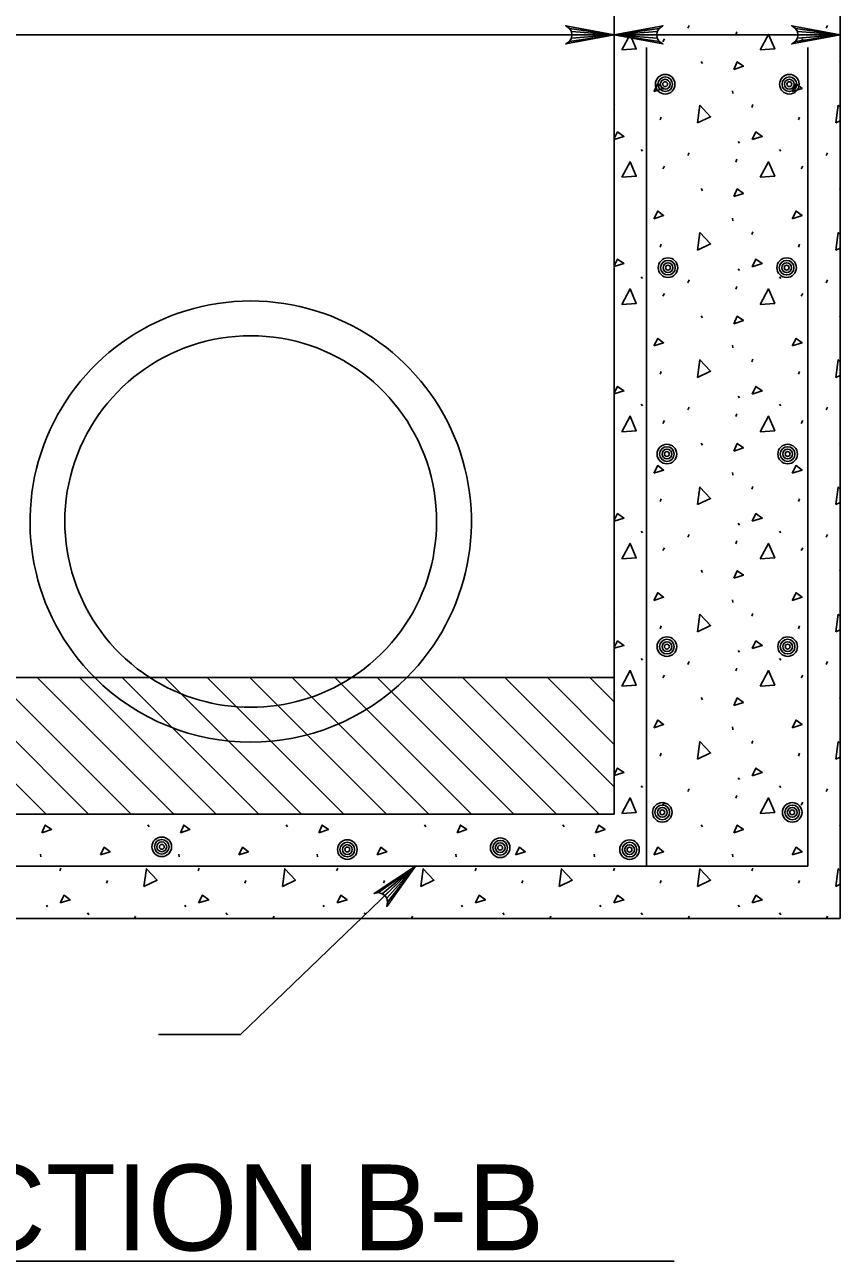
# Model space of a CAD drawing. Extents: x 6.91 to 13.84, y 0.35 to 9.99.
# Drawn here: x 8.532 to 9.481, y 2.3 to 3.739 of the extents above; entities that cross this region are included whole.
import ezdxf

# ---------------------------------------------------------------- set-up
doc = ezdxf.new("R2010")
doc.units = 0
for name, color, linetype in [('Default', 7, 'Continuous'), ('DETL-DIMS', 7, 'Continuous'), ('DETL-LINE', 7, 'Continuous'), ('DETL-TITL', 7, 'Continuous')]:
    doc.layers.add(name, color=color, linetype=linetype)

msp = doc.modelspace()

# ---------------------------------------------------------------- linework, layer by layer
at = {"layer": 'Default'}
for p, q in [((9.3039, 3.7353), (9.3055, 3.7386)), ((9.3599, 3.7277), (9.3611, 3.7309)), ((9.465, 3.7353), (9.4666, 3.7386)), ((9.2749, 3.7196), (9.2766, 3.7229)), ((9.436, 3.7196), (9.4376, 3.7229)), ((9.3196, 3.6967), (9.3212, 3.6943)), ((9.4807, 3.6967), (9.4813, 3.6957)), ((9.3559, 3.6625), (9.3563, 3.6593)), ((9.2184, 3.6458), (9.2186, 3.6464)), ((9.3784, 3.6431), (9.3796, 3.6464)), ((9.2717, 3.6287), (9.2729, 3.6319)), ((9.4328, 3.6287), (9.434, 3.6319)), ((9.4813, 3.6274), (9.4762, 3.625)), ((9.3627, 3.6033), (9.3639, 3.6013)), ((9.2496, 3.594), (9.2512, 3.592)), ((9.3039, 3.5872), (9.3055, 3.5904)), ((9.4106, 3.594), (9.4122, 3.592)), ((9.465, 3.5872), (9.4666, 3.5904)), ((9.2749, 3.5715), (9.2766, 3.5747)), ((9.3599, 3.5795), (9.3611, 3.5828)), ((9.436, 3.5715), (9.4376, 3.5747)), ((9.3196, 3.5485), (9.3212, 3.5461)), ((9.4807, 3.5485), (9.4813, 3.5476)), ((9.3559, 3.5143), (9.3563, 3.5111)), ((9.2184, 3.4977), (9.2186, 3.4982)), ((9.3784, 3.495), (9.3796, 3.4982)), ((9.2717, 3.4805), (9.2729, 3.4837)), ((9.4328, 3.4805), (9.434, 3.4837)), ((9.4813, 3.4793), (9.4762, 3.4769)), ((9.2496, 3.4459), (9.2512, 3.4439)), ((9.3039, 3.439), (9.3055, 3.4423)), ((9.3627, 3.4551), (9.3639, 3.4531)), ((9.4106, 3.4459), (9.4122, 3.4439)), ((9.465, 3.439), (9.4666, 3.4423)), ((9.3599, 3.4314), (9.3611, 3.4346)), ((9.2749, 3.4233), (9.2766, 3.4266)), ((9.436, 3.4233), (9.4376, 3.4266)), ((9.3196, 3.4004), (9.3212, 3.398)), ((9.4807, 3.4004), (9.4813, 3.3994)), ((9.3559, 3.3662), (9.3563, 3.363)), ((9.2184, 3.3495), (9.2186, 3.3501)), ((9.3784, 3.3469), (9.3796, 3.3501)), ((9.2717, 3.3324), (9.2729, 3.3356)), ((9.4328, 3.3324), (9.434, 3.3356)), ((9.4813, 3.3311), (9.4762, 3.3287)), ((9.2496, 3.2977), (9.2512, 3.2957)), ((9.3627, 3.307), (9.3639, 3.305)), ((9.4106, 3.2977), (9.4122, 3.2957)), ((9.3039, 3.2909), (9.3055, 3.2941)), ((9.3599, 3.2832), (9.3611, 3.2865)), ((9.465, 3.2909), (9.4666, 3.2941)), ((9.2749, 3.2752), (9.2766, 3.2784)), ((9.436, 3.2752), (9.4376, 3.2784)), ((9.3196, 3.2522), (9.3212, 3.2498)), ((9.4807, 3.2522), (9.4813, 3.2513)), ((9.3559, 3.218), (9.3563, 3.2148)), ((9.2184, 3.2014), (9.2186, 3.2019)), ((9.3784, 3.1987), (9.3796, 3.2019)), ((9.2717, 3.1842), (9.2729, 3.1874)), ((9.4328, 3.1842), (9.434, 3.1874)), ((9.4813, 3.183), (9.4762, 3.1806)), ((9.3627, 3.1589), (9.3639, 3.1568)), ((9.2496, 3.1496), (9.2512, 3.1476)), ((9.3039, 3.1427), (9.3055, 3.146)), ((9.4106, 3.1496), (9.4122, 3.1476)), ((9.465, 3.1427), (9.4666, 3.146)), ((9.2749, 3.127), (9.2766, 3.1303)), ((9.3599, 3.1351), (9.3611, 3.1383)), ((9.436, 3.127), (9.4376, 3.1303)), ((9.3196, 3.1041), (9.3212, 3.1017)), ((9.4807, 3.1041), (9.4813, 3.1031)), ((9.3559, 3.0699), (9.3563, 3.0667)), ((9.2184, 3.0532), (9.2186, 3.0538)), ((9.3784, 3.0506), (9.3796, 3.0538)), ((9.2717, 3.0361), (9.2729, 3.0393)), ((9.4328, 3.0361), (9.434, 3.0393)), ((9.4813, 3.0349), (9.4762, 3.0324)), ((9.3627, 3.0107), (9.3639, 3.0087)), ((9.2496, 3.0014), (9.2512, 2.9994)), ((9.3039, 2.9946), (9.3055, 2.9978)), ((9.4106, 3.0014), (9.4122, 2.9994)), ((9.465, 2.9946), (9.4666, 2.9978)), ((9.2749, 2.9789), (9.2766, 2.9821)), ((9.3599, 2.987), (9.3611, 2.9902)), ((9.436, 2.9789), (9.4376, 2.9821)), ((8.3982, 2.9792), (8.5572, 2.8202)), ((8.4477, 2.9792), (8.6067, 2.8202)), ((8.4972, 2.9792), (8.6562, 2.8202)), ((8.5467, 2.9792), (8.7057, 2.8202)), ((8.5962, 2.9792), (8.7552, 2.8202)), ((8.6457, 2.9792), (8.8047, 2.8202)), ((8.6952, 2.9792), (8.8542, 2.8202)), ((8.7447, 2.9792), (8.9037, 2.8202)), ((8.7942, 2.9792), (8.9532, 2.8202)), ((8.8436, 2.9792), (9.0027, 2.8202)), ((8.8931, 2.9792), (9.0522, 2.8202)), ((8.9426, 2.9792), (9.1016, 2.8202)), ((8.9921, 2.9792), (9.1511, 2.8202)), ((9.0416, 2.9792), (9.2006, 2.8202)), ((9.0911, 2.9792), (9.2184, 2.852)), ((9.1406, 2.9792), (9.2184, 2.9015)), ((9.1901, 2.9792), (9.2184, 2.951)), ((9.3196, 2.956), (9.3212, 2.9535)), ((9.4807, 2.956), (9.4813, 2.955)), ((9.3559, 2.9217), (9.3563, 2.9185)), ((9.2184, 2.9051), (9.2186, 2.9056)), ((9.3784, 2.9024), (9.3796, 2.9056)), ((9.2717, 2.8879), (9.2729, 2.8911)), ((9.4328, 2.8879), (9.434, 2.8911)), ((9.4813, 2.8867), (9.4762, 2.8843)), ((9.2496, 2.8533), (9.2512, 2.8513)), ((9.3627, 2.8626), (9.3639, 2.8605)), ((9.4106, 2.8533), (9.4122, 2.8513)), ((9.3039, 2.8465), (9.3055, 2.8497)), ((9.3599, 2.8388), (9.3611, 2.842)), ((9.465, 2.8465), (9.4666, 2.8497)), ((9.2749, 2.8308), (9.2766, 2.834)), ((9.436, 2.8308), (9.4376, 2.834)), ((8.6755, 2.8078), (8.6771, 2.8054)), ((8.8365, 2.8078), (8.8382, 2.8054)), ((8.9976, 2.8078), (8.9992, 2.8054)), ((9.1586, 2.8078), (9.1602, 2.8054)), ((9.3196, 2.8078), (9.3212, 2.8054)), ((9.4807, 2.8078), (9.4813, 2.8068)), ((8.5507, 2.7736), (8.5511, 2.7704)), ((8.7117, 2.7736), (8.7121, 2.7704)), ((8.8728, 2.7736), (8.8732, 2.7704)), ((9.0338, 2.7736), (9.0342, 2.7704)), ((9.1948, 2.7736), (9.1952, 2.7704)), ((9.3559, 2.7736), (9.3563, 2.7704)), ((8.5733, 2.7543), (8.5745, 2.7575)), ((8.7343, 2.7543), (8.7355, 2.7575)), ((8.8953, 2.7543), (8.8965, 2.7575)), ((9.0563, 2.7543), (9.0576, 2.7575)), ((9.2174, 2.7543), (9.2186, 2.7575)), ((9.3784, 2.7543), (9.3796, 2.7575)), ((8.6276, 2.7398), (8.6288, 2.743)), ((8.7886, 2.7398), (8.7898, 2.743)), ((8.9497, 2.7398), (8.9509, 2.743)), ((9.1107, 2.7398), (9.1119, 2.743)), ((9.2717, 2.7398), (9.2729, 2.743)), ((9.4328, 2.7398), (9.434, 2.743)), ((9.4813, 2.7386), (9.4762, 2.7361)), ((8.5576, 2.7144), (8.5588, 2.7124)), ((8.7186, 2.7144), (8.7198, 2.7124)), ((8.8796, 2.7144), (8.8808, 2.7124)), ((9.0406, 2.7144), (9.0419, 2.7124)), ((9.2017, 2.7144), (9.2029, 2.7124)), ((9.3627, 2.7144), (9.3639, 2.7124)), ((8.6055, 2.7052), (8.6071, 2.7031)), ((8.6601, 2.6989), (8.6614, 2.7015)), ((8.7665, 2.7052), (8.7681, 2.7031)), ((8.8211, 2.6989), (8.8225, 2.7015)), ((8.9275, 2.7052), (8.9291, 2.7031)), ((8.9822, 2.6989), (8.9835, 2.7015)), ((9.0886, 2.7052), (9.0902, 2.7031)), ((9.1432, 2.6989), (9.1445, 2.7015)), ((9.2496, 2.7052), (9.2512, 2.7031)), ((9.3042, 2.6989), (9.3055, 2.7015)), ((9.4106, 2.7052), (9.4122, 2.7031)), ((9.4652, 2.6989), (9.4666, 2.7015))]:
    msp.add_line(p, q, dxfattribs=at)
for points in [[(9.227, 3.71), (9.2367, 3.7281), (9.2439, 3.7112), (9.227, 3.71)], [(9.3881, 3.71), (9.3977, 3.7281), (9.405, 3.7112), (9.3881, 3.71)], [(9.3575, 3.6874), (9.3615, 3.6963), (9.3687, 3.6911), (9.3575, 3.6874)], [(9.2645, 3.6617), (9.2689, 3.6705), (9.2757, 3.6653), (9.2645, 3.6617)], [(9.4255, 3.6617), (9.4299, 3.6705), (9.4368, 3.6653), (9.4255, 3.6617)], [(9.3152, 3.625), (9.318, 3.6456), (9.3305, 3.6323), (9.3152, 3.625)], [(9.4762, 3.625), (9.479, 3.6456), (9.4813, 3.6432)], [(9.2184, 3.6069), (9.2222, 3.6146), (9.2295, 3.6093), (9.2184, 3.6059)], [(9.3788, 3.6057), (9.3832, 3.6146), (9.3905, 3.6093), (9.3788, 3.6057)], [(9.227, 3.5618), (9.2367, 3.5799), (9.2439, 3.563), (9.227, 3.5618)], [(9.3881, 3.5618), (9.3977, 3.5799), (9.405, 3.563), (9.3881, 3.5618)], [(9.3575, 3.5393), (9.3615, 3.5481), (9.3687, 3.5429), (9.3575, 3.5393)], [(9.2645, 3.5135), (9.2689, 3.5224), (9.2757, 3.5171), (9.2645, 3.5135)], [(9.4255, 3.5135), (9.4299, 3.5224), (9.4368, 3.5171), (9.4255, 3.5135)], [(9.3152, 3.4769), (9.318, 3.4974), (9.3305, 3.4841), (9.3152, 3.4769)], [(9.4762, 3.4769), (9.479, 3.4974), (9.4813, 3.495)], [(9.2184, 3.4588), (9.2222, 3.4664), (9.2295, 3.4612), (9.2184, 3.4577)], [(9.3788, 3.4576), (9.3832, 3.4664), (9.3905, 3.4612), (9.3788, 3.4576)], [(9.227, 3.4137), (9.2367, 3.4318), (9.2439, 3.4149), (9.227, 3.4137)], [(9.3881, 3.4137), (9.3977, 3.4318), (9.405, 3.4149), (9.3881, 3.4137)], [(9.3575, 3.3911), (9.3615, 3.4), (9.3687, 3.3948), (9.3575, 3.3911)], [(9.2645, 3.3654), (9.2689, 3.3742), (9.2757, 3.369), (9.2645, 3.3654)], [(9.4255, 3.3654), (9.4299, 3.3742), (9.4368, 3.369), (9.4255, 3.3654)], [(9.3152, 3.3287), (9.318, 3.3493), (9.3305, 3.336), (9.3152, 3.3287)], [(9.4762, 3.3287), (9.479, 3.3493), (9.4813, 3.3469)], [(9.2184, 3.3106), (9.2222, 3.3183), (9.2295, 3.313), (9.2184, 3.3096)], [(9.3788, 3.3094), (9.3832, 3.3183), (9.3905, 3.313), (9.3788, 3.3094)], [(9.227, 3.2655), (9.2367, 3.2836), (9.2439, 3.2667), (9.227, 3.2655)], [(9.3881, 3.2655), (9.3977, 3.2836), (9.405, 3.2667), (9.3881, 3.2655)], [(9.3575, 3.243), (9.3615, 3.2518), (9.3687, 3.2466), (9.3575, 3.243)], [(9.2645, 3.2172), (9.2689, 3.2261), (9.2757, 3.2208), (9.2645, 3.2172)], [(9.4255, 3.2172), (9.4299, 3.2261), (9.4368, 3.2208), (9.4255, 3.2172)], [(9.3152, 3.1806), (9.318, 3.2011), (9.3305, 3.1878), (9.3152, 3.1806)], [(9.4762, 3.1806), (9.479, 3.2011), (9.4813, 3.1987)], [(9.2184, 3.1625), (9.2222, 3.1701), (9.2295, 3.1649), (9.2184, 3.1615)], [(9.3788, 3.1613), (9.3832, 3.1701), (9.3905, 3.1649), (9.3788, 3.1613)], [(9.227, 3.1174), (9.2367, 3.1355), (9.2439, 3.1186), (9.227, 3.1174)], [(9.3881, 3.1174), (9.3977, 3.1355), (9.405, 3.1186), (9.3881, 3.1174)], [(9.3575, 3.0948), (9.3615, 3.1037), (9.3687, 3.0985), (9.3575, 3.0948)], [(9.2645, 3.0691), (9.2689, 3.0779), (9.2757, 3.0727), (9.2645, 3.0691)], [(9.4255, 3.0691), (9.4299, 3.0779), (9.4368, 3.0727), (9.4255, 3.0691)], [(9.3152, 3.0324), (9.318, 3.053), (9.3305, 3.0397), (9.3152, 3.0324)], [(9.4762, 3.0324), (9.479, 3.053), (9.4813, 3.0506)], [(9.2184, 3.0143), (9.2222, 3.022), (9.2295, 3.0167), (9.2184, 3.0133)], [(9.3788, 3.0131), (9.3832, 3.022), (9.3905, 3.0167), (9.3788, 3.0131)], [(9.227, 2.9692), (9.2367, 2.9874), (9.2439, 2.9704), (9.227, 2.9692)], [(9.3881, 2.9692), (9.3977, 2.9874), (9.405, 2.9704), (9.3881, 2.9692)], [(9.3575, 2.9467), (9.3615, 2.9556), (9.3687, 2.9503), (9.3575, 2.9467)], [(9.2645, 2.9209), (9.2689, 2.9298), (9.2757, 2.9246), (9.2645, 2.9209)], [(9.4255, 2.9209), (9.4299, 2.9298), (9.4368, 2.9246), (9.4255, 2.9209)], [(9.3152, 2.8843), (9.318, 2.9048), (9.3305, 2.8915), (9.3152, 2.8843)], [(9.4762, 2.8843), (9.479, 2.9048), (9.4813, 2.9024)], [(9.2184, 2.8662), (9.2222, 2.8738), (9.2295, 2.8686), (9.2184, 2.8652)], [(9.3788, 2.865), (9.3832, 2.8738), (9.3905, 2.8686), (9.3788, 2.865)], [(9.227, 2.8211), (9.2367, 2.8392), (9.2439, 2.8223), (9.227, 2.8211)], [(9.3881, 2.8211), (9.3977, 2.8392), (9.405, 2.8223), (9.3881, 2.8211)], [(8.5523, 2.7985), (8.5563, 2.8074), (8.5636, 2.8022), (8.5523, 2.7985)], [(8.7134, 2.7985), (8.7174, 2.8074), (8.7246, 2.8022), (8.7134, 2.7985)], [(8.8744, 2.7985), (8.8784, 2.8074), (8.8857, 2.8022), (8.8744, 2.7985)], [(9.0354, 2.7985), (9.0394, 2.8074), (9.0467, 2.8022), (9.0354, 2.7985)], [(9.1964, 2.7985), (9.2005, 2.8074), (9.2077, 2.8022), (9.1964, 2.7985)], [(9.3575, 2.7985), (9.3615, 2.8074), (9.3687, 2.8022), (9.3575, 2.7985)], [(8.6204, 2.7728), (8.6248, 2.7816), (8.6316, 2.7764), (8.6204, 2.7728)], [(8.7814, 2.7728), (8.7858, 2.7816), (8.7927, 2.7764), (8.7814, 2.7728)], [(8.9424, 2.7728), (8.9468, 2.7816), (8.9537, 2.7764), (8.9424, 2.7728)], [(9.1034, 2.7728), (9.1079, 2.7816), (9.1147, 2.7764), (9.1034, 2.7728)], [(9.2645, 2.7728), (9.2689, 2.7816), (9.2757, 2.7764), (9.2645, 2.7728)], [(9.4255, 2.7728), (9.4299, 2.7816), (9.4368, 2.7764), (9.4255, 2.7728)], [(8.6711, 2.7361), (8.6739, 2.7567), (8.6864, 2.7434), (8.6711, 2.7361)], [(8.8321, 2.7361), (8.8349, 2.7567), (8.8474, 2.7434), (8.8321, 2.7361)], [(8.9931, 2.7361), (8.996, 2.7567), (9.0084, 2.7434), (8.9931, 2.7361)], [(9.1542, 2.7361), (9.157, 2.7567), (9.1695, 2.7434), (9.1542, 2.7361)], [(9.3152, 2.7361), (9.318, 2.7567), (9.3305, 2.7434), (9.3152, 2.7361)], [(9.4762, 2.7361), (9.479, 2.7567), (9.4813, 2.7543)], [(8.5737, 2.7168), (8.5781, 2.7257), (8.5853, 2.7204), (8.5737, 2.7168)], [(8.7347, 2.7168), (8.7391, 2.7257), (8.7464, 2.7204), (8.7347, 2.7168)], [(8.8957, 2.7168), (8.9001, 2.7257), (8.9074, 2.7204), (8.8957, 2.7168)], [(9.0567, 2.7168), (9.0612, 2.7257), (9.0684, 2.7204), (9.0567, 2.7168)], [(9.2178, 2.7168), (9.2222, 2.7257), (9.2295, 2.7204), (9.2178, 2.7168)], [(9.3788, 2.7168), (9.3832, 2.7257), (9.3905, 2.7204), (9.3788, 2.7168)]]:
    msp.add_lwpolyline(points, dxfattribs=at)
at = {"layer": 'DETL-DIMS'}
for p, q in [((8.3487, 3.7276), (9.2184, 3.7276)), ((9.2184, 3.7276), (9.4813, 3.7276)), ((8.7835, 2.5636), (8.9869, 2.7596)), ((8.7835, 2.5636), (8.6878, 2.5636))]:
    msp.add_line(p, q, dxfattribs=at)
for points in [[(9.2184, 3.7276), (9.1618, 3.717), (9.1662, 3.72), (9.1684, 3.7238), (9.1691, 3.7276), (9.1684, 3.7314), (9.1662, 3.7351), (9.1618, 3.7382), (9.2184, 3.7276), (9.1662, 3.7351), (9.1684, 3.7314), (9.2184, 3.7276), (9.1691, 3.7276), (9.1684, 3.7238), (9.2184, 3.7276), (9.1662, 3.72)], [(9.2184, 3.7276), (9.2749, 3.717), (9.2706, 3.72), (9.2683, 3.7238), (9.2677, 3.7276), (9.2683, 3.7314), (9.2706, 3.7351), (9.2749, 3.7382), (9.2184, 3.7276), (9.2706, 3.7351), (9.2683, 3.7314), (9.2184, 3.7276), (9.2677, 3.7276), (9.2683, 3.7238), (9.2184, 3.7276), (9.2706, 3.72)], [(9.4813, 3.7276), (9.4248, 3.7382), (9.4291, 3.7351), (9.4314, 3.7314), (9.432, 3.7276), (9.4314, 3.7238), (9.4291, 3.72), (9.4248, 3.717), (9.4813, 3.7276), (9.4291, 3.72), (9.4314, 3.7238), (9.4813, 3.7276), (9.432, 3.7276), (9.4314, 3.7314), (9.4813, 3.7276), (9.4291, 3.7351)], [(8.9869, 2.7596), (8.9535, 2.7127), (8.9546, 2.7179), (8.9536, 2.7222), (8.9514, 2.7254), (8.9483, 2.7276), (8.9441, 2.7288), (8.9388, 2.728), (8.9869, 2.7596), (8.9441, 2.7288), (8.9483, 2.7276), (8.9869, 2.7596), (8.9514, 2.7254), (8.9536, 2.7222), (8.9869, 2.7596), (8.9546, 2.7179)]]:
    msp.add_lwpolyline(points, dxfattribs=at)
at = {"layer": 'DETL-LINE'}
for p, q in [((9.4813, 4.5192), (9.4813, 2.6989)), ((9.2184, 2.8202), (9.2184, 4.0742)), ((9.256, 2.7596), (9.256, 3.7127)), ((9.4437, 2.7596), (9.4437, 3.7127)), ((8.3487, 2.9792), (9.2184, 2.9792)), ((8.3487, 2.8202), (9.2184, 2.8202)), ((8.3063, 2.7596), (9.256, 2.7596)), ((9.4437, 2.7596), (9.256, 2.7596)), ((8.0857, 2.6989), (9.4813, 2.6989))]:
    msp.add_line(p, q, dxfattribs=at)
for centre, radius in [((9.2776, 3.6701), 0.0114), ((9.2776, 3.6701), 0.00853), ((9.2776, 3.6701), 0.00569), ((9.2776, 3.6701), 0.00284), ((9.4221, 3.6701), 0.0114), ((9.4221, 3.6701), 0.00853), ((9.4221, 3.6701), 0.00569), ((9.4221, 3.6701), 0.00284), ((9.2808, 3.4565), 0.0114), ((9.2808, 3.4565), 0.00853), ((9.2808, 3.4565), 0.00569), ((9.2808, 3.4565), 0.00284), ((9.4189, 3.4565), 0.0114), ((9.4189, 3.4565), 0.00853), ((9.4189, 3.4565), 0.00569), ((9.4189, 3.4565), 0.00284), ((9.2796, 3.2395), 0.0114), ((9.2796, 3.2395), 0.00853), ((9.2796, 3.2395), 0.00569), ((9.2796, 3.2395), 0.00284), ((9.4201, 3.2395), 0.0114), ((9.4201, 3.2395), 0.00853), ((9.4201, 3.2395), 0.00569), ((9.4201, 3.2395), 0.00284), ((9.2796, 3.0153), 0.0114), ((9.2796, 3.0153), 0.00853), ((9.4201, 3.0153), 0.0114), ((9.4201, 3.0153), 0.00853), ((9.2796, 3.0153), 0.00569), ((9.2796, 3.0153), 0.00284), ((9.4201, 3.0153), 0.00569), ((9.4201, 3.0153), 0.00284), ((9.2742, 2.8223), 0.0114), ((9.2742, 2.8223), 0.00853), ((9.2742, 2.8223), 0.00569), ((9.2742, 2.8223), 0.00284), ((9.4254, 2.8223), 0.0114), ((9.4254, 2.8223), 0.00853), ((9.4254, 2.8223), 0.00569), ((9.4254, 2.8223), 0.00284), ((8.6918, 2.7822), 0.0114), ((8.6918, 2.7822), 0.00853), ((8.6918, 2.7822), 0.00569), ((8.6918, 2.7822), 0.00284), ((8.9077, 2.779), 0.0114), ((8.9077, 2.779), 0.00853), ((8.9077, 2.779), 0.00569), ((8.9077, 2.779), 0.00284), ((9.0856, 2.7811), 0.0114), ((9.0856, 2.7811), 0.00853), ((9.0856, 2.7811), 0.00569), ((9.0856, 2.7811), 0.00284), ((9.2361, 2.7789), 0.0114), ((9.2361, 2.7789), 0.00853), ((9.2361, 2.7789), 0.00569), ((9.2361, 2.7789), 0.00284)]:
    msp.add_circle(centre, radius, dxfattribs=at)
for radius, start, end in [(0.2568, 314.9704, 225.0296), (0.2163, 302.8847, 237.1153), (0.2568, 225.0296, 314.9704), (0.2163, 237.1153, 302.8847)]:
    msp.add_arc((8.7953, 3.1609), radius, start, end, dxfattribs=at)
at = {"layer": 'DETL-TITL'}
msp.add_line((8.2789, 2.2996), (9.2881, 2.2996), dxfattribs=at)

# ---------------------------------------------------------------- texts
msp.add_text('SECTION B-B', height=0.100117, dxfattribs=at).set_placement((8.2814, 2.3122))

doc.saveas('drawing.dxf')
